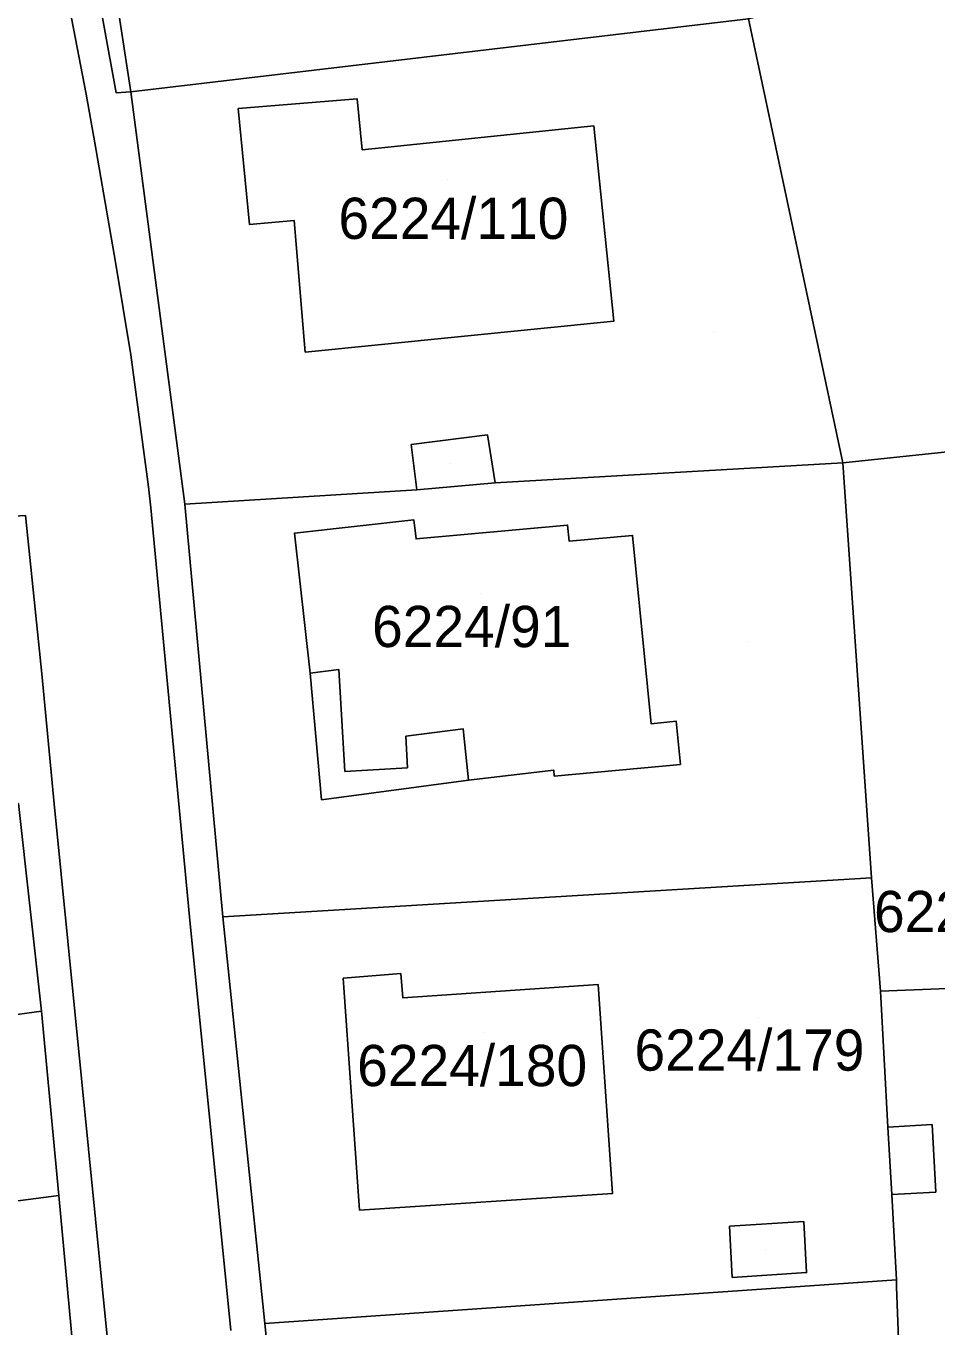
# Model space of a CAD drawing. Extents: x -266199 to -261993, y -1239047 to -1235108.
# Drawn here: x -263836.6 to -263792.5, y -1236026.7 to -1235963.6 of the extents above; entities that cross this region are included whole.
import ezdxf

# ---------------------------------------------------------------- set-up
doc = ezdxf.new("R2010")
doc.units = 0
for name, color, linetype in [('body_kn', 7, 'Continuous'), ('kladpar_druhypozemkov', 7, 'Continuous'), ('kladpar_hranice', 7, 'Continuous'), ('kladpar_parcelnecisla', 7, 'Continuous'), ('kladpar_plochy', 7, 'Continuous'), ('zappar_hrandruhpozemk', 7, 'Continuous')]:
    doc.layers.add(name, color=color, linetype=linetype)

msp = doc.modelspace()

# ---------------------------------------------------------------- linework, layer by layer
at = {"layer": 'body_kn'}
for p, q in [((-263833.72, -1235966.85), (-263833.72, -1235966.85)), ((-263832.26, -1235966.8), (-263832.26, -1235966.8)), ((-263831.56, -1235966.75), (-263831.56, -1235966.75)), ((-263831.56, -1235966.75), (-263831.56, -1235966.75)), ((-263820.58, -1235967.08), (-263820.58, -1235967.08)), ((-263826.35, -1235967.56), (-263826.35, -1235967.56)), ((-263826.35, -1235967.56), (-263826.35, -1235967.56)), ((-263809.1, -1235968.39), (-263809.1, -1235968.39)), ((-263833.31, -1235969.22), (-263833.31, -1235969.22)), ((-263820.34, -1235969.55), (-263820.34, -1235969.55)), ((-263825.8, -1235973.18), (-263825.8, -1235973.18)), ((-263823.64, -1235972.98), (-263823.64, -1235972.98)), ((-263832.3, -1235975), (-263832.3, -1235975)), ((-263808.13, -1235977.87), (-263808.13, -1235977.87)), ((-263831.56, -1235979.51), (-263831.56, -1235979.51)), ((-263823.1, -1235979.37), (-263823.1, -1235979.37)), ((-263814.26, -1235983.38), (-263814.26, -1235983.38)), ((-263817.96, -1235983.86), (-263817.96, -1235983.86)), ((-263797.02, -1235984.75), (-263797.02, -1235984.75)), ((-263830.7, -1235985.9), (-263830.7, -1235985.9)), ((-263817.69, -1235986.06), (-263817.69, -1235986.06)), ((-263817.69, -1235986.06), (-263817.69, -1235986.06)), ((-263813.88, -1235985.72), (-263813.88, -1235985.72)), ((-263828.93, -1235986.75), (-263828.93, -1235986.75)), ((-263830.58, -1235986.93), (-263830.58, -1235986.93)), ((-263817.83, -1235987.5), (-263817.83, -1235987.5)), ((-263810.37, -1235987.76), (-263810.37, -1235987.76)), ((-263823.61, -1235988.15), (-263823.61, -1235988.15)), ((-263817.72, -1235988.43), (-263817.72, -1235988.43)), ((-263810.3, -1235988.54), (-263810.3, -1235988.54)), ((-263807.22, -1235988.26), (-263807.22, -1235988.26)), ((-263822.85, -1235994.94), (-263822.85, -1235994.94)), ((-263822.85, -1235994.94), (-263822.85, -1235994.94)), ((-263821.46, -1235994.77), (-263821.46, -1235994.77)), ((-263835.87, -1235994.98), (-263835.87, -1235994.98)), ((-263806.32, -1235997.4), (-263806.32, -1235997.4)), ((-263805.1, -1235997.28), (-263805.1, -1235997.28)), ((-263818.21, -1235998.01), (-263818.21, -1235998.01)), ((-263815.44, -1235997.64), (-263815.44, -1235997.64)), ((-263804.9, -1235999.37), (-263804.9, -1235999.37)), ((-263821.17, -1235999.72), (-263821.17, -1235999.72)), ((-263818.13, -1235999.54), (-263818.13, -1235999.54)), ((-263811.04, -1235999.65), (-263811.04, -1235999.65)), ((-263811.03, -1235999.95), (-263811.03, -1235999.95)), ((-263815.17, -1236000.13), (-263815.17, -1236000.13)), ((-263822.31, -1236001.09), (-263822.31, -1236001.09)), ((-263822.31, -1236001.09), (-263822.31, -1236001.09)), ((-263835.28, -1236001.29), (-263835.28, -1236001.29)), ((-263795.63, -1236004.87), (-263795.63, -1236004.87)), ((-263795.63, -1236004.87), (-263795.63, -1236004.87)), ((-263828.71, -1236006.77), (-263828.71, -1236006.77)), ((-263827.09, -1236006.76), (-263827.09, -1236006.76)), ((-263821.25, -1236009.75), (-263821.25, -1236009.75)), ((-263821.25, -1236009.75), (-263821.25, -1236009.75)), ((-263818.46, -1236009.52), (-263818.46, -1236009.52)), ((-263808.89, -1236010.05), (-263808.89, -1236010.05)), ((-263818.36, -1236010.7), (-263818.36, -1236010.7)), ((-263795.19, -1236010.38), (-263795.19, -1236010.38)), ((-263795.19, -1236010.38), (-263795.19, -1236010.38)), ((-263835.89, -1236011.35), (-263835.89, -1236011.35)), ((-263835.89, -1236011.35), (-263835.89, -1236011.35)), ((-263794.83, -1236016.97), (-263794.83, -1236016.97)), ((-263792.69, -1236016.85), (-263792.69, -1236016.85)), ((-263808.2, -1236020.19), (-263808.2, -1236020.19)), ((-263792.51, -1236020.12), (-263792.51, -1236020.12)), ((-263835.05, -1236020.28), (-263835.05, -1236020.28)), ((-263835.05, -1236020.28), (-263835.05, -1236020.28)), ((-263794.65, -1236020.24), (-263794.65, -1236020.24)), ((-263794.65, -1236020.24), (-263794.65, -1236020.24)), ((-263820.47, -1236020.99), (-263820.47, -1236020.99)), ((-263802.51, -1236021.77), (-263802.51, -1236021.77)), ((-263798.91, -1236021.54), (-263798.91, -1236021.54)), ((-263802.39, -1236024.27), (-263802.39, -1236024.27)), ((-263802.39, -1236024.27), (-263802.39, -1236024.27)), ((-263798.78, -1236024.03), (-263798.78, -1236024.03)), ((-263794.42, -1236024.38), (-263794.42, -1236024.38)), ((-263794.41, -1236024.72), (-263794.41, -1236024.72)), ((-263825.05, -1236026.49), (-263825.05, -1236026.49))]:
    msp.add_line(p, q, dxfattribs=at)
at = {"layer": 'kladpar_druhypozemkov'}
for p, q in [((-263816.19, -1235970.99), (-263816.19, -1235970.99)), ((-263803.3, -1235978.44), (-263803.3, -1235978.44)), ((-263816.07, -1235984.77), (-263816.07, -1235984.77)), ((-263814.58, -1235991.08), (-263814.58, -1235991.08)), ((-263801.58, -1235993.43), (-263801.58, -1235993.43)), ((-263801.12, -1236011.63), (-263801.12, -1236011.63)), ((-263814.46, -1236012.38), (-263814.46, -1236012.38)), ((-263800.77, -1236022.92), (-263800.77, -1236022.92))]:
    msp.add_line(p, q, dxfattribs=at)
at = {"layer": 'kladpar_hranice'}
for points in [[(-263801.6, -1235963.2), (-263831.56, -1235966.75), (-263836.32, -1235935.66), (-263802.25, -1235933.04), (-263801.6, -1235963.2)], [(-263836.32, -1235935.66), (-263831.56, -1235966.75), (-263828.93, -1235986.75), (-263827.09, -1236006.76), (-263825.05, -1236026.49), (-263824.66, -1236030.52), (-263824.61, -1236031.06), (-263823.14, -1236046.4), (-263821.18, -1236066.45), (-263819.01, -1236085.37), (-263816.94, -1236103.98), (-263814.26, -1236125.61), (-263809.51, -1236162.58), (-263806.98, -1236167.3), (-263802.64, -1236169.58), (-263797.21, -1236169.95), (-263795.11, -1236169.28), (-263793.47, -1236168.16), (-263792.21, -1236166.68), (-263790.66, -1236167.31), (-263784.63, -1236167.79), (-263782.95, -1236167.92), (-263781.27, -1236168.05), (-263778.88, -1236168.41)], [(-263789.48, -1235983.95), (-263797.02, -1235984.75), (-263801.6, -1235963.2), (-263778.63, -1235957.54), (-263773.39, -1235956.45), (-263768.96, -1235955.6), (-263767.35, -1235955.29), (-263765.34, -1235966.31), (-263767.83, -1235966.37), (-263768.27, -1235966.38), (-263790.44, -1235967.49), (-263790.14, -1235972.52), (-263790.03, -1235974.32), (-263789.48, -1235983.95)], [(-263833.28, -1236039.34), (-263835.05, -1236020.28), (-263840.03, -1236020.93), (-263841.03, -1236014.36), (-263841.37, -1236012.08), (-263835.89, -1236011.35), (-263837.01, -1236001.27), (-263842.92, -1236002.08), (-263843.97, -1235995.5), (-263837.52, -1235994.78), (-263838.31, -1235987.4), (-263841.01, -1235970.09), (-263850.48, -1235972.43), (-263852.3, -1235965.99), (-263852.92, -1235963.79), (-263842.67, -1235961.04)], [(-263801.6, -1235963.2), (-263797.02, -1235984.75), (-263813.88, -1235985.72), (-263817.69, -1235986.06), (-263828.93, -1235986.75), (-263831.56, -1235966.75), (-263801.6, -1235963.2)], [(-263782.59, -1236009.87), (-263795.19, -1236010.38), (-263795.63, -1236004.87), (-263797.02, -1235984.75), (-263789.48, -1235983.95), (-263789.32, -1235986.67), (-263789.28, -1235987.5), (-263790.54, -1235987.47), (-263790.24, -1235992.81), (-263789, -1235992.74), (-263788.92, -1235993.8), (-263788.28, -1236003.91), (-263783.13, -1236003.65), (-263782.59, -1236009.87)], [(-263795.63, -1236004.87), (-263827.09, -1236006.76), (-263828.93, -1235986.75), (-263817.69, -1235986.06), (-263813.88, -1235985.72), (-263797.02, -1235984.75), (-263795.63, -1236004.87)], [(-263852.47, -1236003.2), (-263846.75, -1236002.53), (-263842.92, -1236002.08), (-263837.01, -1236001.27), (-263835.89, -1236011.35), (-263841.37, -1236012.08), (-263850.83, -1236013.33), (-263852.47, -1236003.2)], [(-263795.19, -1236010.38), (-263794.83, -1236016.97), (-263794.65, -1236020.24), (-263794.42, -1236024.38), (-263825.05, -1236026.49), (-263827.09, -1236006.76), (-263795.63, -1236004.87), (-263795.19, -1236010.38)], [(-263818.46, -1236009.52), (-263821.25, -1236009.75), (-263820.47, -1236020.99), (-263808.2, -1236020.19), (-263808.89, -1236010.05), (-263818.36, -1236010.7), (-263818.46, -1236009.52)], [(-263821.25, -1236009.75), (-263818.46, -1236009.52), (-263818.36, -1236010.7), (-263808.89, -1236010.05), (-263808.2, -1236020.19), (-263820.47, -1236020.99), (-263821.25, -1236009.75)], [(-263782.59, -1236009.87), (-263782.18, -1236015.98), (-263787.07, -1236016.15), (-263786.76, -1236023.48), (-263786.3, -1236023.46), (-263782.07, -1236023.27), (-263781.64, -1236032.94), (-263794.09, -1236033.17), (-263794.41, -1236024.72), (-263794.42, -1236024.38), (-263794.65, -1236020.24), (-263794.83, -1236016.97), (-263795.19, -1236010.38), (-263782.59, -1236009.87)], [(-263835.05, -1236020.28), (-263833.28, -1236039.34), (-263860.75, -1236038.65), (-263861.24, -1236038.62), (-263861.02, -1236037.94), (-263854.11, -1236037.98), (-263854.63, -1236033.02), (-263847.98, -1236032.21), (-263849.53, -1236022.05), (-263843.83, -1236021.38), (-263840.03, -1236020.93), (-263835.05, -1236020.28)], [(-263824.66, -1236030.52), (-263825.05, -1236026.49), (-263794.42, -1236024.38), (-263794.41, -1236024.72), (-263794.09, -1236033.17)]]:
    msp.add_lwpolyline(points, dxfattribs=at)
at = {"layer": 'kladpar_plochy'}
for p, q in [((-263827.09, -1236006.76), (-263795.63, -1236004.87)), ((-263795.63, -1236004.87), (-263795.19, -1236010.38)), ((-263825.05, -1236026.49), (-263827.09, -1236006.76)), ((-263818.46, -1236009.52), (-263821.25, -1236009.75)), ((-263821.25, -1236009.75), (-263820.47, -1236020.99)), ((-263818.36, -1236010.7), (-263818.46, -1236009.52)), ((-263808.89, -1236010.05), (-263818.36, -1236010.7)), ((-263808.2, -1236020.19), (-263808.89, -1236010.05)), ((-263795.19, -1236010.38), (-263794.83, -1236016.97)), ((-263794.83, -1236016.97), (-263794.65, -1236020.24)), ((-263820.47, -1236020.99), (-263808.2, -1236020.19)), ((-263794.65, -1236020.24), (-263794.42, -1236024.38)), ((-263794.42, -1236024.38), (-263825.05, -1236026.49))]:
    msp.add_line(p, q, dxfattribs=at)
for points in [[(-263801.6, -1235963.2), (-263831.56, -1235966.75), (-263836.32, -1235935.66), (-263802.25, -1235933.04)], [(-263789.48, -1235983.95), (-263797.02, -1235984.75), (-263801.6, -1235963.2), (-263778.63, -1235957.54), (-263773.39, -1235956.45), (-263768.96, -1235955.6), (-263767.35, -1235955.29), (-263765.34, -1235966.31), (-263767.83, -1235966.37), (-263768.27, -1235966.38), (-263790.44, -1235967.49), (-263790.14, -1235972.52), (-263790.03, -1235974.32)], [(-263801.6, -1235963.2), (-263797.02, -1235984.75), (-263813.88, -1235985.72), (-263817.69, -1235986.06), (-263828.93, -1235986.75), (-263831.56, -1235966.75)], [(-263782.59, -1236009.87), (-263795.19, -1236010.38), (-263795.63, -1236004.87), (-263797.02, -1235984.75), (-263789.48, -1235983.95), (-263789.32, -1235986.67), (-263789.28, -1235987.5), (-263790.54, -1235987.47), (-263790.24, -1235992.81), (-263789, -1235992.74), (-263788.92, -1235993.8), (-263788.28, -1236003.91), (-263783.13, -1236003.65)], [(-263795.63, -1236004.87), (-263827.09, -1236006.76), (-263828.93, -1235986.75), (-263817.69, -1235986.06), (-263813.88, -1235985.72), (-263797.02, -1235984.75)], [(-263852.47, -1236003.2), (-263846.75, -1236002.53), (-263842.92, -1236002.08), (-263837.01, -1236001.27), (-263835.89, -1236011.35), (-263841.37, -1236012.08), (-263850.83, -1236013.33)], [(-263821.25, -1236009.75), (-263818.46, -1236009.52), (-263818.36, -1236010.7), (-263808.89, -1236010.05), (-263808.2, -1236020.19), (-263820.47, -1236020.99)], [(-263782.59, -1236009.87), (-263782.18, -1236015.98), (-263787.07, -1236016.15), (-263786.76, -1236023.48), (-263786.3, -1236023.46), (-263782.07, -1236023.27), (-263781.64, -1236032.94), (-263794.09, -1236033.17), (-263794.41, -1236024.72), (-263794.42, -1236024.38), (-263794.65, -1236020.24), (-263794.83, -1236016.97), (-263795.19, -1236010.38)], [(-263835.05, -1236020.28), (-263833.28, -1236039.34), (-263860.75, -1236038.65), (-263861.24, -1236038.62), (-263861.02, -1236037.94), (-263854.11, -1236037.98), (-263854.63, -1236033.02), (-263847.98, -1236032.21), (-263849.53, -1236022.05), (-263843.83, -1236021.38), (-263840.03, -1236020.93)]]:
    msp.add_lwpolyline(points, close=True, dxfattribs=at)
for points in [[(-263836.32, -1235935.66), (-263831.56, -1235966.75), (-263828.93, -1235986.75), (-263827.09, -1236006.76), (-263825.05, -1236026.49), (-263824.66, -1236030.52), (-263824.61, -1236031.06), (-263823.14, -1236046.4), (-263821.18, -1236066.45), (-263819.01, -1236085.37), (-263816.94, -1236103.98), (-263814.26, -1236125.61), (-263809.51, -1236162.58), (-263806.98, -1236167.3), (-263802.64, -1236169.58), (-263797.21, -1236169.95), (-263795.11, -1236169.28), (-263793.47, -1236168.16), (-263792.21, -1236166.68)], [(-263833.28, -1236039.34), (-263835.05, -1236020.28), (-263840.03, -1236020.93), (-263841.03, -1236014.36), (-263841.37, -1236012.08), (-263835.89, -1236011.35), (-263837.01, -1236001.27), (-263842.92, -1236002.08), (-263843.97, -1235995.5), (-263837.52, -1235994.78), (-263838.31, -1235987.4), (-263841.01, -1235970.09), (-263850.48, -1235972.43), (-263852.3, -1235965.99), (-263852.92, -1235963.79), (-263842.67, -1235961.04)], [(-263824.66, -1236030.52), (-263825.05, -1236026.49), (-263794.42, -1236024.38), (-263794.41, -1236024.72), (-263794.09, -1236033.17)]]:
    msp.add_lwpolyline(points, dxfattribs=at)
at = {"layer": 'zappar_hrandruhpozemk'}
for p, q in [((-263809.1, -1235968.39), (-263820.34, -1235969.55)), ((-263817.96, -1235983.86), (-263814.26, -1235983.38)), ((-263814.26, -1235983.38), (-263813.88, -1235985.72)), ((-263817.69, -1235986.06), (-263817.96, -1235983.86)), ((-263830.58, -1235986.93), (-263828.71, -1236006.77)), ((-263804.9, -1235999.37), (-263811.03, -1235999.95)), ((-263821.17, -1235999.72), (-263818.13, -1235999.54)), ((-263835.28, -1236001.29), (-263831.51, -1236039.17)), ((-263828.71, -1236006.77), (-263826.71, -1236026.84)), ((-263835.89, -1236011.35), (-263835.05, -1236020.28)), ((-263792.69, -1236016.85), (-263794.83, -1236016.97)), ((-263792.51, -1236020.12), (-263792.69, -1236016.85)), ((-263794.65, -1236020.24), (-263792.51, -1236020.12)), ((-263798.91, -1236021.54), (-263802.51, -1236021.77)), ((-263802.51, -1236021.77), (-263802.39, -1236024.27))]:
    msp.add_line(p, q, dxfattribs=at)
for points in [[(-263836.62, -1235951.29), (-263835.57, -1235957.28), (-263833.72, -1235966.85), (-263833.31, -1235969.22), (-263832.3, -1235975), (-263831.56, -1235979.51), (-263830.7, -1235985.9), (-263830.58, -1235986.93)], [(-263831.56, -1235966.75), (-263832.26, -1235966.8), (-263834.06, -1235956.93)], [(-263820.34, -1235969.55), (-263820.58, -1235967.08), (-263826.35, -1235967.56)], [(-263826.35, -1235967.56), (-263825.8, -1235973.18), (-263823.64, -1235972.98), (-263823.1, -1235979.37), (-263808.13, -1235977.87), (-263809.1, -1235968.39)], [(-263838.31, -1235987.4), (-263836.66, -1235987.3), (-263835.87, -1235994.98), (-263835.28, -1236001.29)], [(-263822.85, -1235994.94), (-263823.61, -1235988.15), (-263817.83, -1235987.5), (-263817.72, -1235988.43), (-263810.37, -1235987.76), (-263810.3, -1235988.54), (-263807.22, -1235988.26), (-263806.32, -1235997.4), (-263805.1, -1235997.28), (-263804.9, -1235999.37)], [(-263822.31, -1236001.09), (-263822.85, -1235994.94), (-263821.46, -1235994.77), (-263821.17, -1235999.72)], [(-263818.13, -1235999.54), (-263818.21, -1235998.01), (-263815.44, -1235997.64), (-263815.17, -1236000.13), (-263822.31, -1236001.09)], [(-263811.03, -1235999.95), (-263811.04, -1235999.65), (-263815.17, -1236000.13)], [(-263802.39, -1236024.27), (-263798.78, -1236024.03), (-263798.91, -1236021.54)]]:
    msp.add_lwpolyline(points, dxfattribs=at)

# ---------------------------------------------------------------- texts
at = {"layer": 'kladpar_parcelnecisla'}
for s, p in [('6224/110', (-263821.488, -1235973.88)), ('6224/91', (-263819.855, -1235993.68)), ('6224/285', (-263795.508, -1236007.51)), ('6224/179', (-263807.128, -1236014.23)), ('6224/180', (-263820.579, -1236014.98))]:
    msp.add_text(s, height=2, dxfattribs=at).set_placement(p)

doc.saveas('drawing.dxf')
